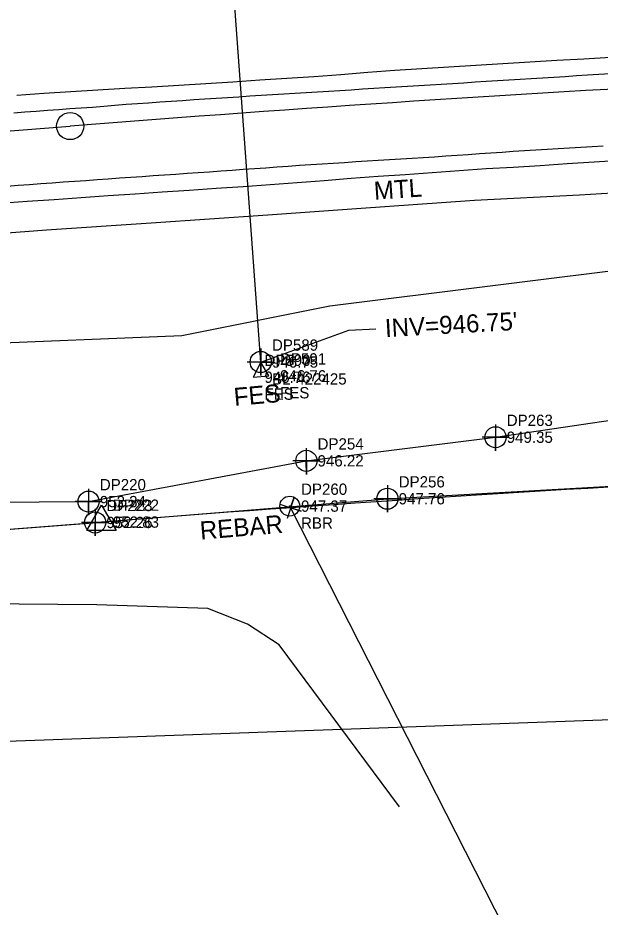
# Model space of a CAD drawing. Extents: x 1182322 to 1186765, y 572295 to 575411.
# Drawn here: x 1184883.7 to 1185012.8, y 573627.9 to 573824.9 of the extents above; entities that cross this region are included whole.
import ezdxf

# ---------------------------------------------------------------- set-up
doc = ezdxf.new("R2010")
doc.units = 0
for name, color, linetype in [('COGO Default Chain', 7, 'Continuous'), ('Default Symbol Cogo Comment', 7, 'Continuous'), ('Default Symbol Cogo Elevation', 7, 'Continuous'), ('Default Symbol Cogo Number', 7, 'Continuous'), ('Exist Guardrail', 7, 'Continuous'), ('Exist Guardrail Text', 7, 'Continuous'), ('Exist Horizontal Alignment', 7, 'Continuous'), ('Exist Horizontal Alignment Point', 7, 'Continuous'), ('Exist Other Culture Fence Line', 7, 'Continuous'), ('Exist Other Culture Fence Line Cogo Elevation', 7, 'Continuous'), ('Exist Other Culture Fence Line Cogo Number', 7, 'Continuous'), ('Exist Other Culture Fence Line Cogo Point CELL', 7, 'Continuous'), ('Exist Property Corner CELL', 7, 'Continuous'), ('Exist Property Iron Pin CELL', 7, 'Continuous'), ('Exist Property Iron Pin Cogo Comment', 7, 'Continuous'), ('Exist Property Iron Pin Cogo Elevation', 7, 'Continuous'), ('Exist Property Iron Pin Cogo Number', 7, 'Continuous'), ('Exist Property Iron Pin Text', 7, 'Continuous'), ('Exist Property Line', 7, 'Continuous'), ('Exist Right of Way Line', 7, 'Continuous'), ('Exist Right of Way Monument CELL', 7, 'Continuous'), ('Exist Right of Way Monument Cogo Elevation', 7, 'Continuous'), ('Exist Right of Way Monument Cogo Number', 7, 'Continuous'), ('Exist Roads EOP', 7, 'Continuous'), ('Exist Roads EOP Other', 7, 'Continuous'), ('Exist Roads EOP Other Text', 7, 'Continuous'), ('Exist Roads EOT', 7, 'Continuous'), ('Exist Structure Minor Pipes RCP 24 Inch', 7, 'Continuous'), ('Exist Structure Minor Pipes RCP 24 Inch Cogo Comment', 7, 'Continuous'), ('Exist Structure Minor Pipes RCP 24 Inch Cogo Elevation', 7, 'Continuous'), ('Exist Structure Minor Pipes RCP 24 Inch Cogo Number', 7, 'Continuous'), ('Exist Structure Minor Pipes RCP 24 Inch Cogo Point CELL', 7, 'Continuous'), ('Exist Structure Minor Pipes RCP 24 Inch Invert', 7, 'Continuous'), ('Exist Structure Minor Pipes RCP 24 Inch Leader', 7, 'Continuous'), ('Exist Utilities Telephone UG Conduit SUE LOS B', 7, 'Continuous'), ('Exist Utilities Telephone UG Conduit SUE LOS B Cogo Elevation', 7, 'Continuous'), ('Exist Utilities Telephone UG Conduit SUE LOS B Cogo Number', 7, 'Continuous'), ('Exist Utilities Telephone UG Conduit SUE LOS B Cogo Point CELL', 7, 'Continuous'), ('Exist Vegetation Woods Line', 7, 'Continuous'), ('Sheet Layout Plan Border', 7, 'Continuous')]:
    doc.layers.add(name, color=color, linetype=linetype)

msp = doc.modelspace()

# ---------------------------------------------------------------- linework, layer by layer
at = {"layer": 'COGO Default Chain'}
msp.add_line((1184314.88, 573754.98), (1184895.31, 573800.93), dxfattribs=at)
msp.add_arc((1185332.16, 568282.65), 5535.54, 92.94509, 94.52634, dxfattribs=at)
at = {"layer": 'Exist Guardrail'}
msp.add_lwpolyline([(1185117.88, 573790.32), (1185084.03, 573789.38), (1185056.74, 573788.27), (1185030.15, 573786.97), (1185008.24, 573785.66), (1184984.92, 573784.41), (1184958.75, 573782.63), (1184939.11, 573781.23), (1184913.28, 573779.4), (1184890.07, 573777.86), (1184868.74, 573776.28), (1184850.59, 573775.01), (1184830.97, 573773.4), (1184808.46, 573771.76), (1184780.42, 573769.59), (1184746.98, 573767.19), (1184724.28, 573765.46), (1184696.48, 573763.55), (1184670.09, 573761.5), (1184642.01, 573759.29), (1184614.6, 573757.31), (1184594.84, 573755.66)], dxfattribs=at)
at = {"layer": 'Exist Horizontal Alignment'}
msp.add_line((1184314.88, 573754.98), (1184895.31, 573800.93), dxfattribs=at)
msp.add_arc((1185332.16, 568282.65), 5535.54, 92.94509, 94.52634, dxfattribs=at)
at = {"layer": 'Exist Horizontal Alignment Point'}
msp.add_circle((1184895.31, 573800.93), 3, dxfattribs=at)
at = {"layer": 'Exist Other Culture Fence Line'}
msp.add_lwpolyline([(1184699.34, 573697.51), (1184773.78, 573703.02), (1184848.65, 573709.06), (1184900.84, 573713.11), (1184965.64, 573718.36), (1185023.1, 573721.56), (1185061.74, 573723.1), (1185125.69, 573725.08), (1185204.48, 573724.02), (1185248.27, 573721.81), (1185300.17, 573718.11), (1185350.66, 573712.74), (1185422.95, 573702.8), (1185464.84, 573695.68), (1185533.29, 573681.7), (1185567.96, 573674.22), (1185634.32, 573659.17)], dxfattribs=at)
at = {"layer": 'Exist Other Culture Fence Line Cogo Point CELL'}
for points in [[(1184965.64, 573721.36), (1184965.64, 573715.36), (1184965.64, 573718.36), (1184968.64, 573718.36), (1184962.64, 573718.36)], [(1184900.84, 573716.11), (1184900.84, 573710.11), (1184900.84, 573713.11), (1184903.84, 573713.11), (1184897.84, 573713.11)]]:
    msp.add_lwpolyline(points, dxfattribs=at)
for centre in [(1184965.64, 573718.36), (1184900.84, 573713.11)]:
    msp.add_circle(centre, 2.34, dxfattribs=at)
at = {"layer": 'Exist Property Corner CELL'}
msp.add_line((1184944.17, 573716.36), (1184944.17, 573716.36), dxfattribs=at)
msp.add_lwpolyline([(1184941.8, 573717.13), (1184946.55, 573715.59), (1184944.17, 573716.36), (1184944.95, 573718.74), (1184943.4, 573713.98)], dxfattribs=at)
at = {"layer": 'Exist Property Iron Pin CELL'}
for radius in [2.2, 0.0707]:
    msp.add_circle((1184943.99, 573716.73), radius, dxfattribs=at)
at = {"layer": 'Exist Property Line'}
msp.add_line((1184944.17, 573716.36), (1185223.78, 573167.05), dxfattribs=at)
at = {"layer": 'Exist Right of Way Line'}
msp.add_line((1184312.49, 573666.52), (1184902.25, 573713.2), dxfattribs=at)
msp.add_arc((1185332.16, 568282.65), 5447.54, 92.94509, 94.52634, dxfattribs=at)
at = {"layer": 'Exist Right of Way Monument CELL'}
msp.add_line((1184902.27, 573713.19), (1184902.27, 573713.19), dxfattribs=at)
msp.add_lwpolyline([(1184899.02, 573711.3), (1184902.27, 573716.94), (1184905.51, 573711.3)], close=True, dxfattribs=at)
at = {"layer": 'Exist Roads EOP'}
for points in [[(1184883.48, 573807.81), (1184889.46, 573808.23), (1184895.45, 573808.59), (1184901.44, 573808.95), (1184907.43, 573809.31), (1184913.42, 573809.66), (1184919.41, 573810.02), (1184925.39, 573810.38), (1184931.38, 573810.76), (1184937.37, 573811.15), (1184943.36, 573811.54), (1184949.34, 573811.92), (1184955.33, 573812.36), (1184961.31, 573812.85), (1184967.29, 573813.33), (1184973.28, 573813.71), (1184979.26, 573814.09), (1184985.25, 573814.46), (1184991.24, 573814.83), (1184997.23, 573815.2), (1185003.22, 573815.53), (1185009.21, 573815.85), (1185015.2, 573816.17)], [(1185017.44, 573793.29), (1185011.45, 573792.97), (1185005.46, 573792.56), (1184999.48, 573792.16), (1184993.49, 573791.79), (1184987.5, 573791.44), (1184981.52, 573791.04), (1184975.53, 573790.61), (1184969.55, 573790.17), (1184963.56, 573789.73), (1184957.58, 573789.29), (1184951.6, 573788.83), (1184945.62, 573788.38), (1184939.63, 573787.93), (1184933.65, 573787.51), (1184927.66, 573787.09), (1184921.68, 573786.67), (1184915.69, 573786.26), (1184909.71, 573785.86), (1184903.72, 573785.45), (1184897.74, 573785.03), (1184891.75, 573784.62), (1184885.77, 573784.21), (1184879.78, 573783.79)]]:
    msp.add_lwpolyline(points, dxfattribs=at)
at = {"layer": 'Exist Roads EOP Other'}
msp.add_lwpolyline([(1184937.55, 573748.66), (1184935.87, 573745.29), (1184939.33, 573745.6)], close=True, dxfattribs=at)
at = {"layer": 'Exist Roads EOT'}
for points in [[(1185015, 573812.48), (1185012.51, 573812.33), (1185010.01, 573812.19), (1185007.52, 573812.04), (1185005.02, 573811.88), (1185002.53, 573811.72), (1185000.03, 573811.57), (1184997.54, 573811.41), (1184995.04, 573811.25), (1184992.55, 573811.1), (1184990.05, 573810.94), (1184987.56, 573810.79), (1184985.06, 573810.63), (1184982.57, 573810.47), (1184980.07, 573810.31), (1184977.58, 573810.16), (1184975.08, 573810.01), (1184972.59, 573809.86), (1184970.09, 573809.71), (1184967.6, 573809.55), (1184965.1, 573809.4), (1184962.61, 573809.24), (1184960.11, 573809.08), (1184957.62, 573808.92), (1184955.12, 573808.76), (1184952.63, 573808.6), (1184950.13, 573808.44), (1184947.64, 573808.29), (1184945.14, 573808.13), (1184942.65, 573807.98), (1184940.15, 573807.83), (1184937.66, 573807.68), (1184935.16, 573807.53), (1184932.67, 573807.37), (1184930.17, 573807.22), (1184927.68, 573807.06), (1184925.18, 573806.89), (1184922.69, 573806.72), (1184920.2, 573806.54), (1184917.7, 573806.38), (1184915.21, 573806.21), (1184912.71, 573806.05), (1184910.22, 573805.88), (1184907.73, 573805.69), (1184905.23, 573805.49), (1184902.74, 573805.29), (1184900.25, 573805.09), (1184897.76, 573804.91), (1184895.26, 573804.73), (1184892.77, 573804.56), (1184890.28, 573804.38), (1184887.78, 573804.2), (1184885.29, 573804), (1184882.8, 573803.8)], [(1185013.5, 573796.46), (1185011.01, 573796.32), (1185008.51, 573796.16), (1185006.02, 573796.01), (1185003.52, 573795.89), (1185001.03, 573795.76), (1184998.53, 573795.61), (1184996.04, 573795.45), (1184993.54, 573795.28), (1184991.05, 573795.11), (1184988.55, 573794.93), (1184986.06, 573794.76), (1184983.57, 573794.58), (1184981.07, 573794.41), (1184978.58, 573794.24), (1184976.09, 573794.07), (1184973.59, 573793.91), (1184971.1, 573793.75), (1184968.6, 573793.6), (1184966.11, 573793.44), (1184963.61, 573793.29), (1184961.12, 573793.14), (1184958.62, 573792.98), (1184956.13, 573792.82), (1184953.63, 573792.66), (1184951.14, 573792.49), (1184948.64, 573792.33), (1184946.15, 573792.17), (1184943.65, 573792), (1184941.16, 573791.82), (1184938.67, 573791.64), (1184936.17, 573791.46), (1184933.68, 573791.28), (1184931.19, 573791.11), (1184928.69, 573790.93), (1184926.2, 573790.76), (1184923.71, 573790.59), (1184921.21, 573790.42), (1184918.72, 573790.24), (1184916.22, 573790.06), (1184913.73, 573789.89), (1184911.24, 573789.72), (1184908.74, 573789.54), (1184906.25, 573789.37), (1184903.76, 573789.19), (1184901.26, 573789.01), (1184898.77, 573788.82), (1184896.28, 573788.65), (1184893.78, 573788.48), (1184891.29, 573788.3), (1184888.79, 573788.11), (1184886.3, 573787.93), (1184883.81, 573787.75), (1184881.31, 573787.57)]]:
    msp.add_lwpolyline(points, dxfattribs=at)
at = {"layer": 'Exist Structure Minor Pipes RCP 24 Inch'}
msp.add_line((1184937.55, 573748.66), (1184928.34, 573875.15), dxfattribs=at)
at = {"layer": 'Exist Structure Minor Pipes RCP 24 Inch Cogo Point CELL'}
msp.add_lwpolyline([(1184937.55, 573751.66), (1184937.55, 573745.66), (1184937.55, 573748.66), (1184940.55, 573748.66), (1184934.55, 573748.66)], dxfattribs=at)
msp.add_circle((1184937.55, 573748.66), 2.34, dxfattribs=at)
at = {"layer": 'Exist Structure Minor Pipes RCP 24 Inch Leader'}
msp.add_lwpolyline([(1184937.55, 573748.66), (1184957.1, 573755.69), (1184963.09, 573756.02)], dxfattribs=at)
at = {"layer": 'Exist Utilities Telephone UG Conduit SUE LOS B'}
msp.add_lwpolyline([(1184705.2, 573717.51), (1184761.61, 573719.92), (1184808.75, 573719.14), (1184855.63, 573717.48), (1184899.38, 573717.73), (1184947.65, 573726.76), (1184989.59, 573731.99), (1185049.6, 573740.86), (1185104.23, 573742.11), (1185147.54, 573741.49), (1185190.99, 573738.17), (1185243.67, 573733.83), (1185296.19, 573730.81), (1185343.76, 573727.54), (1185391.61, 573722.1), (1185423.08, 573716.53), (1185467.66, 573711.88), (1185536.39, 573704.97), (1185583.2, 573696.39), (1185626.44, 573682.88)], dxfattribs=at)
at = {"layer": 'Exist Utilities Telephone UG Conduit SUE LOS B Cogo Point CELL'}
for points in [[(1184989.57, 573734.81), (1184989.61, 573728.99), (1184989.59, 573731.99), (1184992.61, 573731.99), (1184986.61, 573731.99)], [(1184947.64, 573729.57), (1184947.67, 573723.76), (1184947.65, 573726.76), (1184950.67, 573726.76), (1184944.67, 573726.76)], [(1184899.36, 573720.54), (1184899.39, 573714.73), (1184899.38, 573717.73), (1184902.39, 573717.73), (1184896.39, 573717.73)]]:
    msp.add_lwpolyline(points, dxfattribs=at)
for centre in [(1184989.61, 573731.99), (1184947.67, 573726.76), (1184899.39, 573717.73)]:
    msp.add_circle(centre, 2.34, dxfattribs=at)
at = {"layer": 'Exist Vegetation Woods Line'}
for points in [[(1184575.02, 573729.05), (1184597.15, 573732.62), (1184637.97, 573736.65), (1184706.19, 573743.8), (1184765.1, 573753.09), (1184813.5, 573755.42), (1184873.05, 573752.61), (1184920.1, 573754.56), (1184952.91, 573761.14), (1185024.52, 573770.05), (1185065.05, 573766.23), (1185104.79, 573771.63), (1185125.52, 573775.21), (1185166.8, 573773.18), (1185213.51, 573768.99), (1185272.49, 573771.32), (1185349.48, 573766.46), (1185397.23, 573756.66)], [(1184968.3, 573650.1), (1184941.62, 573685.96), (1184934.59, 573690.54), (1184925.83, 573694.02), (1184901.23, 573694.88), (1184840.86, 573695.34), (1184757.06, 573690.04), (1184664.95, 573681.51), (1184647.63, 573680.01), (1184636.86, 573667.49), (1184627.1, 573662.78), (1184609.64, 573663.77), (1184590.4, 573677.89), (1184572.68, 573673.49), (1184560.54, 573677.73), (1184540.44, 573682.61)]]:
    msp.add_lwpolyline(points, dxfattribs=at)
at = {"layer": 'Sheet Layout Plan Border'}
msp.add_line((1184830.48, 573662.79), (1185374.39, 573682.41), dxfattribs=at)

# ---------------------------------------------------------------- texts
at = {"layer": 'Default Symbol Cogo Comment'}
for p in [(1184938.37, 573740.29), (1184941.83, 573740.6)]:
    msp.add_text('FES', height=2.5, dxfattribs=at).set_placement(p)
at = {"layer": 'Default Symbol Cogo Elevation'}
for p in [(1184938.37, 573744.04), (1184941.83, 573744.35)]:
    msp.add_text('946.76', height=2.5, dxfattribs=at).set_placement(p)
at = {"layer": 'Default Symbol Cogo Number'}
for s, p in [('DP590', (1184938.37, 573747.79)), ('DP591', (1184941.83, 573748.1))]:
    msp.add_text(s, height=2.5, dxfattribs=at).set_placement(p)
at = {"layer": 'Exist Guardrail Text'}
msp.add_text('MTL', height=4, rotation=3.8904, dxfattribs=at).set_placement((1184962.77, 573784.61))
at = {"layer": 'Exist Other Culture Fence Line Cogo Elevation'}
for s, p in [('947.76', (1184968.14, 573717.11)), ('952.26', (1184903.34, 573711.86))]:
    msp.add_text(s, height=2.5, dxfattribs=at).set_placement(p)
at = {"layer": 'Exist Other Culture Fence Line Cogo Number'}
for s, p in [('DP256', (1184968.14, 573720.86)), ('DP223', (1184903.34, 573715.61))]:
    msp.add_text(s, height=2.5, dxfattribs=at).set_placement(p)
at = {"layer": 'Exist Property Iron Pin Cogo Comment'}
msp.add_text('RBR', height=2.5, dxfattribs=at).set_placement((1184946.49, 573711.73))
at = {"layer": 'Exist Property Iron Pin Cogo Elevation'}
msp.add_text('947.37', height=2.5, dxfattribs=at).set_placement((1184946.49, 573715.48))
at = {"layer": 'Exist Property Iron Pin Cogo Number'}
msp.add_text('DP260', height=2.5, dxfattribs=at).set_placement((1184946.49, 573719.23))
at = {"layer": 'Exist Property Iron Pin Text'}
msp.add_text('REBAR', height=4, rotation=4.7936, dxfattribs=at).set_placement((1184924.24, 573709.29))
at = {"layer": 'Exist Right of Way Monument Cogo Elevation'}
msp.add_text('952.83', height=2.5, dxfattribs=at).set_placement((1184904.77, 573711.94))
at = {"layer": 'Exist Right of Way Monument Cogo Number'}
msp.add_text('DP222', height=2.5, dxfattribs=at).set_placement((1184904.77, 573715.69))
at = {"layer": 'Exist Roads EOP Other Text'}
msp.add_text('FES', height=4, rotation=5.0878, dxfattribs=at).set_placement((1184931.76, 573738.9))
at = {"layer": 'Exist Structure Minor Pipes RCP 24 Inch Cogo Comment'}
msp.add_text('BL*422425', height=2.5, dxfattribs=at).set_placement((1184940.05, 573743.66))
at = {"layer": 'Exist Structure Minor Pipes RCP 24 Inch Cogo Elevation'}
msp.add_text('946.75', height=2.5, dxfattribs=at).set_placement((1184940.05, 573747.41))
at = {"layer": 'Exist Structure Minor Pipes RCP 24 Inch Cogo Number'}
msp.add_text('DP589', height=2.5, dxfattribs=at).set_placement((1184940.05, 573751.16))
at = {"layer": 'Exist Structure Minor Pipes RCP 24 Inch Invert'}
msp.add_text("INV=946.75'", height=4, rotation=3.1853, dxfattribs=at).set_placement((1184965.2, 573754.14))
at = {"layer": 'Exist Utilities Telephone UG Conduit SUE LOS B Cogo Elevation'}
for s, p in [('949.35', (1184992.09, 573730.74)), ('946.22', (1184950.15, 573725.51)), ('952.34', (1184901.88, 573716.48))]:
    msp.add_text(s, height=2.5, dxfattribs=at).set_placement(p)
at = {"layer": 'Exist Utilities Telephone UG Conduit SUE LOS B Cogo Number'}
for s, p in [('DP263', (1184992.09, 573734.49)), ('DP254', (1184950.15, 573729.26)), ('DP220', (1184901.88, 573720.23))]:
    msp.add_text(s, height=2.5, dxfattribs=at).set_placement(p)

doc.saveas('drawing.dxf')
